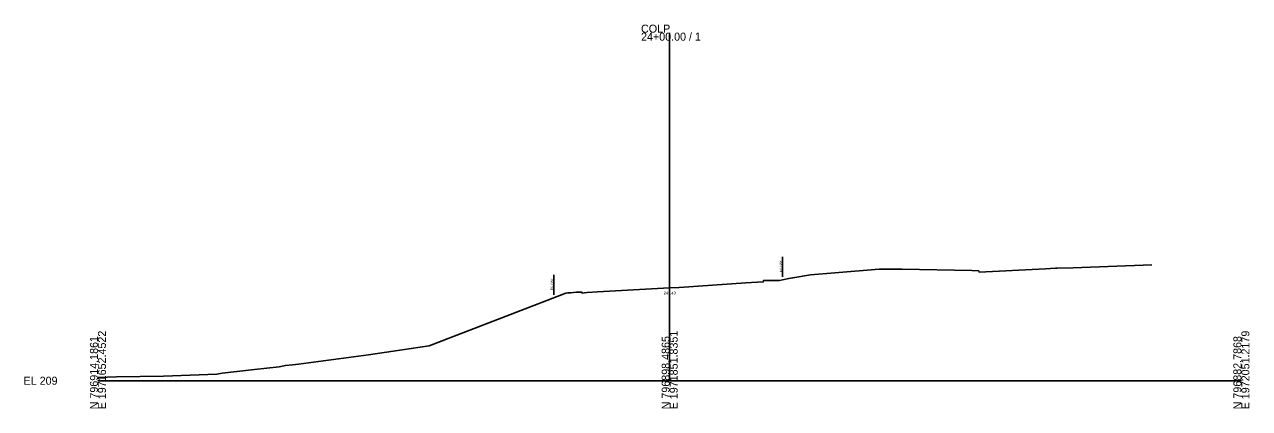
# Model space of a CAD drawing. Extents: x 1936082 to 1978201, y 795649 to 820520.
# Drawn here: x 1977772 to 1978200.5, y 810114.6 to 810248.8 of the extents above; entities that cross this region are included whole.
import ezdxf

# ---------------------------------------------------------------- set-up
doc = ezdxf.new("R2010")
doc.units = 0
for name, color, linetype in [('Default', 7, 'Continuous'), ('RD_GPK_XS_Cell', 7, 'Continuous'), ('RD_XS_ExGround', 7, 'Continuous'), ('RD_XS_ExRW', 7, 'Continuous'), ('RD_XS_TX_Elev_EX', 7, 'Continuous')]:
    doc.layers.add(name, color=color, linetype=linetype)

msp = doc.modelspace()

# ---------------------------------------------------------------- linework, layer by layer
at = {"layer": 'RD_GPK_XS_Cell'}
for p, q in [((1977997.68, 810124.34), (1977997.68, 810245.93)), ((1977797.68, 810124.34), (1977997.68, 810124.34)), ((1977997.68, 810124.34), (1978197.68, 810124.34))]:
    msp.add_line(p, q, dxfattribs=at)
at = {"layer": 'RD_XS_ExGround'}
msp.add_lwpolyline([(1977797.68, 810125.45), (1977804.13, 810125.74), (1977820.61, 810125.89), (1977839.3, 810126.64), (1977841.09, 810126.93), (1977852.44, 810128.23), (1977861.12, 810129.23), (1977863.27, 810129.66), (1977865.78, 810129.88), (1977867.82, 810130.09), (1977887.11, 810132.65), (1977892.33, 810133.42), (1977900.95, 810134.61), (1977913.59, 810136.52), (1977961.36, 810154.94), (1977962.09, 810155.05), (1977963.09, 810155.1), (1977964.92, 810155.22), (1977965.51, 810155.26), (1977966.93, 810155.33), (1977967.03, 810154.93), (1977967.92, 810155.07), (1977968.81, 810155.19), (1977972.41, 810155.38), (1977997.68, 810156.77), (1978001.04, 810156.95), (1978024.37, 810158.52), (1978030.43, 810158.87), (1978030.53, 810159.37), (1978032.03, 810159.37), (1978036.05, 810159.37), (1978037.16, 810159.62), (1978039.37, 810160.07), (1978040.75, 810160.33), (1978046.93, 810161.34), (1978055.45, 810162.02), (1978071.01, 810163.26), (1978074.93, 810163.34), (1978078.97, 810163.31), (1978103.33, 810162.82), (1978105.82, 810162.72), (1978105.93, 810162.32), (1978129.16, 810163.39), (1978132.61, 810163.62), (1978133.27, 810163.66), (1978138.88, 810163.78), (1978166.36, 810164.87)], dxfattribs=at)
at = {"layer": 'RD_XS_ExRW'}
for p, q in [((1978037.12, 810160.61), (1978037.12, 810167.61)), ((1977957.12, 810154.31), (1977957.12, 810161.31))]:
    msp.add_line(p, q, dxfattribs=at)

# ---------------------------------------------------------------- texts
at = {"layer": 'Default'}
msp.add_text('-', height=0.0001, dxfattribs=at).set_placement((1977797.68, 810124.34))
at = {"layer": 'RD_GPK_XS_Cell'}
for s, p in [('COLP', (1977987.68, 810245.93)), ('24+00.00 / 1', (1977987.68, 810243.13)), ('EL 209', (1977771.68, 810122.94))]:
    msp.add_text(s, height=2.8, dxfattribs=at).set_placement(p)
for s, p in [('E 1971652.4522', (1977800.48, 810114.34)), ('E 1971851.8351', (1978000.48, 810114.34)), ('E 1972051.2179', (1978200.48, 810114.34)), ('N 796914.1861', (1977797.68, 810114.34)), ('N 796898.4865', (1977997.68, 810114.34)), ('N 796882.7868', (1978197.68, 810114.34))]:
    msp.add_text(s, height=2.8, rotation=90, dxfattribs=at).set_placement(p)
at = {"layer": 'RD_XS_ExRW'}
for p in [(1978036.86, 810162.29), (1977956.86, 810155.99)]:
    msp.add_text('EX. R/W ', height=0.75, rotation=90, dxfattribs=at).set_placement(p)
at = {"layer": 'RD_XS_TX_Elev_EX'}
msp.add_text('241.43', height=1, dxfattribs=at).set_placement((1977995.6, 810154.46))

doc.saveas('drawing.dxf')
